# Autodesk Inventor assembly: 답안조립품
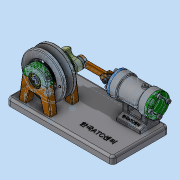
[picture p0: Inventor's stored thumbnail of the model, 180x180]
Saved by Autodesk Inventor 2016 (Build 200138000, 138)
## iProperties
Created: 2018-01
Part Number: 답안조립품
Material: 일반
Document SubType Name: Assembly
Designer: Administrator
Mass: 865.838 g
Surface Area: 888.145 cm^2
Volume: 224.244 cm^3
Density: 3.86115 g/cm^3
Author: Administrator
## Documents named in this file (19)
- C:\Users\Administrator\Desktop\380107V1039\답안조립품.iam
- C:\Users\Administrator\Desktop\380107V1039\3mm 와셔.ipt
- C:\Users\Administrator\Desktop\380107V1039\V-벨트풀리.ipt
- C:\Users\Administrator\Desktop\380107V1039\둥근머리볼트 M3x12.ipt
- C:\Users\Administrator\Desktop\380107V1039\베어링 8x22x7.ipt
- C:\Users\Administrator\Desktop\380107V1039\베어링커버-A.ipt
- C:\Users\Administrator\Desktop\380107V1039\볼트 M3x8.ipt
- C:\Users\Administrator\Desktop\380107V1039\볼트 M3x12.ipt
- C:\Users\Administrator\Desktop\380107V1039\스페이서.ipt
- C:\Users\Administrator\Desktop\380107V1039\지지대-A.ipt
- C:\Users\Administrator\Desktop\380107V1039\커넥팅로드-A.ipt
- C:\Users\Administrator\Desktop\380107V1039\커넥팅로드-B.ipt
- C:\Users\Administrator\Desktop\380107V1039\크랭크축.ipt
- C:\Users\Administrator\Desktop\380107V1039\플랜지.ipt
- C:\Users\Administrator\Desktop\380107V1039\플레이트.ipt
- C:\Users\Administrator\Desktop\380107V1039\피스톤.ipt
- C:\Users\Administrator\Desktop\380107V1039\하우징.ipt
- C:\Users\Administrator\Desktop\380107V1039\하우징커버-A.ipt
- C:\Users\Administrator\Desktop\380107V1039\하우징커버-B.ipt
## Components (9 placed, 8 different names)
1. 3mm 와셔:1
2. 3mm 와셔:2
3. V-벨트풀리:1 — 각도:1, 각도:2
4. 플랜지:1
5. 플레이트:1 — 각도:2
6. 피스톤:1
7. 하우징:1
8. 하우징커버-A:1
9. 하우징커버-B:1
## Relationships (2: Angle 2)
- 각도:1 [Angle]: V-벨트풀리:1
- 각도:2 [Angle]: V-벨트풀리:1 ↔ 플레이트:1
